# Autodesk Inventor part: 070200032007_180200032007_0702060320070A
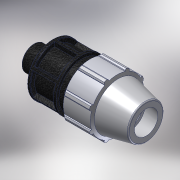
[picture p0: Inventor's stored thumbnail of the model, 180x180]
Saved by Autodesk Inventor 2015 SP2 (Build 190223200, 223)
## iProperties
Created: 2017-02
Part Number: 070200032007_180200032007_0702060320070A
Material: PVC-Piping
Description: PLASSON MALE ADAPTOR 32-3/4"
Document SubType Name: Modeling
Designer: KIM
Mass: 92.6774 g
Surface Area: 199.44 cm^2
Volume: 66.1981 cm^3
Density: 1.4 g/cm^3
Appearance: PTFE
Author: KIM
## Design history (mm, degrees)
derived "07020.ipt"
feature "Solid1::07020.ipt"
tag "TaggingFeature1"
body "Solid1"
other parameters: "d2" = 32, "d4" = 15.14286, "d5" = 26.5, "d7" = 64, "d8" = 48, "d9" = 15.14286, "d11" = 3.02857, "d12" = 51.2, "d13" = 120 deg, "d14" = 48, "d15" = 10 deg, "d16" = 57.6, "d18" = 1.6, "d19" = 35 deg, "d20" = 17.5 deg, "d21" = 59.52, "d23" = 0, "d25" = 360 deg, "d27" = 1.28, "d34" = 3.2, "d36" = 0, "d42" = 26.5, "d43" = 1.92, "d46" = 0.96, "d49" = 83, "d51" = 106, "d52" = 18, "d53" = 0.64, "d55" = 360 deg, "d57" = 26.441, "d58" = 18.5087, "d59" = 21.2, "d_" = 32, "E_" = 64, "H_" = 106, "l_" = 83, "l_2" = 18, "R_" = 26.441
